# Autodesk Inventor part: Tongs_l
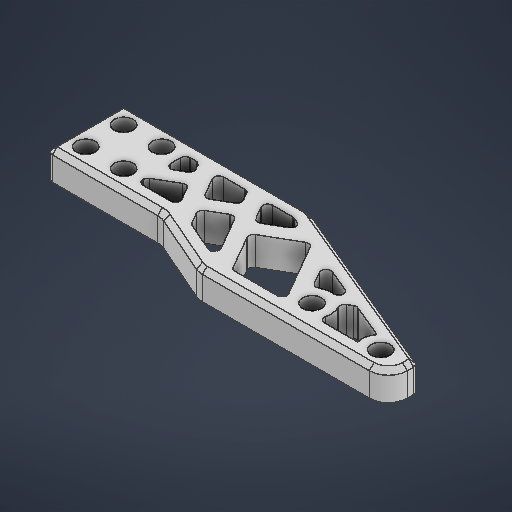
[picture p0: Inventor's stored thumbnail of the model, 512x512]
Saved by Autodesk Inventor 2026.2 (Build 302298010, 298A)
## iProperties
Created: 2026-05
Part Number: Tongs_l
Material: 일반
Document SubType Name: Modeling
Designer: work
Density: 1 g/cm^3
Appearance: 기본값
Author: work
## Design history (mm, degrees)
sketch "스케치1"
  geometry: L1 (-4, 4)-(4, 4); L2 (4, 4)-(4, -4); L3 (4, -4)-(-4, -4); L4 (-4, -4)-(-4, 4); L5 (-4, 4)-(4, -4); L6 (4, 4)-(-4, -4); L7 (-8, 8)-(8, 8); L8 (8, 8)-(8, -8); L9 (8, -8)-(-8, -8); L10 (-8, -8)-(-8, 8); L11 (-8, 8)-(8, -8); L12 (8, 8)-(-8, -8); L13 (-8, 8)-(-16, 8); L14 (-16, 8)-(-29.748, 14); L15 (-29.748, 14)-(-69.748, 14); L16 (-69.748, 14)-(-69.748, 8); L17 (-69.748, 8)-(-31.398, -8); L18 (-31.398, -8)-(-8, -8); L19 (-8, -5)-(-30.797, -5); L20 (-30.797, -5)-(-66.748, 9.999); L21 (-66.748, 9.999)-(-66.748, 11); L22 (-66.748, 11)-(-30.374, 11); L23 (-30.374, 11)-(-16.626, 5); L24 (-16.626, 5)-(-8, 5); L25 (-48.561, 11)-(-42.029, -0.314); L26 (-45.097, 11)-(-37.465, -2.218); L27 (-30.374, 11)-(-21.136, -5); L28 (-33.838, 11)-(-24.6, -5); L29 (-16.626, 5)-(-10.853, -5); L30 (-21.257, 7.021)-(-14.317, -5); L31 (-37.465, -2.218)-(-29.021, 2.657); L32 (-27.521, 0.059)-(-33.982, -3.671); L33 (-13.739, 0)-(-8, 3.314); L34 (-12.239, -2.598)-(-8, -0.15); L35 (-17.787, 1.011)-(-22.902, -1.942); L36 (-24.402, 0.656)-(-19.287, 3.609); L37 (-46.029, 6.614)-(-51.317, 3.561); L38 (-47.029, 8.346)-(-53.639, 4.53); C1 r 2 at (4, 4); C2 r 2 at (4, -4); C3 r 2 at (-4, -4); C4 r 2 at (-4, 4); 4 further points
  constraints: 76 end point, 24 point on line, 19 parallel, 8 midpoint, 6 perpendicular, 4 centre point, 4 coincident, 3 horizontal, 5 other
  dimensions: "d0" = 8 distance of L2.end L3.end; "d1" = 8 distance of L1.end L2.end; "d2" = 4 diameter of C1; "d3" = 4 diameter of C2; "d4" = 4 diameter of C3; "d5" = 4 diameter of C4; "d6" = 4 distance between parallel lines of L8 L2; "d7" = 8 distance of L7.start L13.end; "d8" = 15 distance of L13.end L14.end; "d9" = 40 distance of L14.end L15.end; "d10" = 6 distance of L15.end L16.end; "d11" = 38.34957 horizontal distance of L16.end L17.end; "d12" = 3 distance between parallel lines of L14 L23; "d13" = 3 distance between parallel lines of L25 L26; "d14" = 3 distance between parallel lines of L28 L27; "d15" = 3 distance between parallel lines of L30 L29; "d16" = 120 deg angle of L22 L28; "d17" = 3 distance between parallel lines of L35 L36; "d18" = 3 distance from line of L31 point (-30.752, -1.806); "d19" = 2 distance between parallel lines of L38 L37; "d20" = 8 distance from line of L25.end L37; "d21" = 3 distance between parallel lines of L34 L33
extrude "돌출1" new body sketch "스케치1" distance "d22" = 6; taper "d23" = 0 deg
sketch "스케치2"
  geometry: L1 (16, -8)-(29.748, -14) reference; L2 (29.748, -14)-(69.748, -14) reference; L3 (69.748, -14)-(69.748, -8) reference; L4 (69.748, -8)-(31.398, 8) reference; L5 (31.398, 8)-(-8, 8) reference; L6 (-8, 8)-(-8, -8) reference; L7 (-8, -8)-(16, -8) reference; L8 (27.521, -0.059)-(24.6, 5) reference; L9 (24.6, 5)-(30.797, 5) reference; L10 (30.797, 5)-(33.982, 3.671) reference; L11 (33.982, 3.671)-(27.521, -0.059) reference; L12 (12.239, 2.598)-(8, 0.15) reference; L13 (8, 0.15)-(8, 5) reference; L14 (8, 5)-(10.853, 5) reference; L15 (10.853, 5)-(12.239, 2.598) reference; L16 (17.787, -1.011)-(14.317, 5) reference; L17 (14.317, 5)-(21.136, 5) reference; L18 (21.136, 5)-(22.902, 1.942) reference; L19 (22.902, 1.942)-(17.787, -1.011) reference; L20 (46.029, -6.614)-(42.029, 0.314) reference; L21 (42.029, 0.314)-(51.317, -3.561) reference; L22 (51.317, -3.561)-(46.029, -6.614) reference; L23 (13.739, 0)-(16.626, -5) reference; L24 (16.626, -5)-(8, -5) reference; L25 (8, -5)-(8, -3.314) reference; L26 (8, -3.314)-(13.739, 0) reference; L27 (19.287, -3.609)-(24.402, -0.656) reference; L28 (24.402, -0.656)-(30.374, -11) reference; L29 (30.374, -11)-(21.257, -7.021) reference; L30 (21.257, -7.021)-(19.287, -3.609) reference; L31 (29.021, -2.657)-(37.465, 2.218) reference; L32 (37.465, 2.218)-(45.097, -11) reference; L33 (45.097, -11)-(33.838, -11) reference; L34 (33.838, -11)-(29.021, -2.657) reference; L35 (47.029, -8.346)-(53.639, -4.53) reference; L36 (53.639, -4.53)-(66.748, -9.999) reference; L37 (66.748, -9.999)-(66.748, -11) reference; L38 (66.748, -11)-(48.561, -11) reference; L39 (48.561, -11)-(47.029, -8.346) reference; C1 r 2 at (4, -4) reference; C2 r 2 at (4, 4) reference; C3 r 2 at (-4, 4) reference; C4 r 2 at (-4, -4) reference; 5 further points
  constraints: 4 coincident
hole "구멍1" sketch "스케치2" at (-4, -4), (4, -4), (4, 4), (-4, 4) diameter "d24" = 4; stored, may be unused: countersink angle "d28" = 90 deg, drill point angle "d30" = 118 deg; dims "d25" = 6, "d26" = 6.2, "d27" = 3, "d29" = 8
fillet "모깎기1" dims "d31" = 1
fillet "모깎기2" dims "d32" = 4
fillet "모깎기3" dims "d33" = 1
chamfer "모따기1" distance "d34" = 1; stored, may be unused: second distance "d35" = 2, angle "d36" = 45 deg
node "작업 평면1"
sketch "스케치3"
  geometry: L1 (39.398, 0)-(0, 0) reference; L2 (0, 0)-(80.713, 0); L3 (80.713, 0)-(80.713, 23.103); L4 (80.713, 23.103)-(0, 23.103); L5 (0, 23.103)-(0, 0); 2 further points
  constraints: 8 end point, 2 parallel, 1 horizontal, 1 perpendicular
extrude "돌출2" cut sketch "스케치3" extent not by distance; stored distance "d38" = 10; taper "d39" = 0 deg
fillet "모깎기4" dims "d40" = 1
fillet "모깎기5" dims "d41" = 4
chamfer "모따기2" distance "d42" = 1; stored, may be unused: second distance "d43" = 2, angle "d44" = 45 deg
sketch "스케치4"
  geometry: L1 (77.133, 14.743)-(40.137, -0.692) reference; L2 (77.748, 17)-(77.748, 15.666) reference; L3 (38.583, 21)-(73.748, 21) reference; L4 (24.765, 15.334)-(36.983, 20.666) reference; L5 (1, 15)-(23.165, 15) reference; L6 (0, 0)-(0, 14) reference; L7 (38.597, -1)-(1, -1) reference; L8 (40.232, 4.339)-(36.387, 6.559) reference; L9 (38.982, 2.077)-(40.117, 2.55) reference; L10 (34.332, 2)-(38.597, 2) reference; L11 (35.021, 6.193)-(33.466, 3.5) reference; L12 (16, 5.117)-(16, 3) reference; L13 (19.373, 4.902)-(17.5, 5.984) reference; L14 (19.141, 2.5)-(19.739, 3.536) reference; L15 (17, 2)-(18.275, 2) reference; L16 (30.036, 5.558)-(26.653, 7.511) reference; L17 (29.425, 2.5)-(30.402, 4.192) reference; L18 (24.049, 2)-(28.559, 2) reference; L19 (25.287, 7.145)-(23.183, 3.5) reference; L20 (57.566, 11.572)-(54.895, 13.114) reference; L21 (52.759, 7.825)-(57.451, 9.783) reference; L22 (53.529, 12.748)-(51.508, 9.248) reference; L23 (16.5, 10.025)-(20.873, 7.5) reference; L24 (16, 11)-(16, 10.891) reference; L25 (22.894, 12)-(17, 12) reference; L26 (22.239, 7.866)-(23.76, 10.5) reference; L27 (29.093, 13.736)-(27.787, 11.475) reference; L28 (35.588, 16.784)-(29.559, 14.153) reference; L29 (32.902, 8.522)-(36.854, 15.368) reference; L30 (28.153, 10.109)-(31.536, 8.156) reference; L31 (51.365, 18)-(42.415, 18) reference; L32 (45.965, 5.648)-(52.231, 16.5) reference; L33 (37.887, 9.157)-(44.599, 5.282) reference; L34 (41.549, 17.5)-(37.521, 10.523) reference; L35 (72.153, 18)-(57.138, 18) reference; L36 (62.095, 11.72)-(72.538, 16.077) reference; L37 (55.895, 14.846)-(61.21, 11.777) reference; L38 (56.272, 17.5)-(55.529, 16.212) reference; C1 r 3.1 at (4, 3) reference; C2 r 3.1 at (4, 11) reference; C3 r 3.1 at (12, 11) reference; C4 r 3.1 at (12, 3) reference; C5 r 2 at (56.395, 15.712); C6 r 4 at (56.395, 15.712); C7 r 4 at (72.153, 17); C8 r 2 at (72.153, 17); A1 r 4 centre (38.597, 3) between (38.597, -1) and (40.137, -0.692) reference; A2 r 1 centre (76.748, 15.666) between (77.133, 14.743) and (77.748, 15.666) reference; A3 r 4 centre (73.748, 17) between (77.748, 17) and (73.748, 21) reference; A4 r 4 centre (38.583, 17) between (38.583, 21) and (36.983, 20.666) reference; A5 r 4 centre (23.165, 19) between (23.165, 15) and (24.765, 15.334) reference; A6 r 1 centre (1, 14) between (1, 15) and (0, 14) reference; A7 r 1 centre (1, 0) between (0, 0) and (1, -1) reference; A8 r 1 centre (39.732, 3.473) between (40.117, 2.55) and (40.232, 4.339) reference; A9 r 1 centre (38.597, 3) between (38.597, 2) and (38.982, 2.077) reference; A10 r 1 centre (34.332, 3) between (33.466, 3.5) and (34.332, 2) reference; A11 r 1 centre (35.887, 5.693) between (36.387, 6.559) and (35.021, 6.193) reference; A12 r 1 centre (17, 5.117) between (17.5, 5.984) and (16, 5.117) reference; A13 r 1 centre (18.873, 4.036) between (19.739, 3.536) and (19.373, 4.902) reference; A14 r 1 centre (18.275, 3) between (18.275, 2) and (19.141, 2.5) reference; A15 r 1 centre (17, 3) between (16, 3) and (17, 2) reference; A16 r 1 centre (29.536, 4.692) between (30.402, 4.192) and (30.036, 5.558) reference; A17 r 1 centre (28.559, 3) between (28.559, 2) and (29.425, 2.5) reference; A18 r 1 centre (24.049, 3) between (23.183, 3.5) and (24.049, 2) reference; A19 r 1 centre (26.153, 6.645) between (26.653, 7.511) and (25.287, 7.145) reference; A20 r 1 centre (54.395, 12.248) between (54.895, 13.114) and (53.529, 12.748) reference; A21 r 1 centre (57.066, 10.706) between (57.451, 9.783) and (57.566, 11.572) reference; A22 r 1 centre (52.374, 8.748) between (51.508, 9.248) and (52.759, 7.825) reference; A23 r 1 centre (17, 10.891) between (16, 10.891) and (16.5, 10.025) reference; A24 r 1 centre (17, 11) between (17, 12) and (16, 11) reference; A25 r 1 centre (22.894, 11) between (23.76, 10.5) and (22.894, 12) reference; A26 r 1 centre (21.373, 8.366) between (20.873, 7.5) and (22.239, 7.866) reference; A27 r 1 centre (28.653, 10.975) between (27.787, 11.475) and (28.153, 10.109) reference; A28 r 1 centre (29.959, 13.236) between (29.559, 14.153) and (29.093, 13.736) reference; A29 r 1 centre (35.988, 15.868) between (36.854, 15.368) and (35.588, 16.784) reference; A30 r 1 centre (32.036, 9.022) between (31.536, 8.156) and (32.902, 8.522) reference; A31 r 1 centre (51.365, 17) between (52.231, 16.5) and (51.365, 18) reference; A32 r 1 centre (45.099, 6.148) between (44.599, 5.282) and (45.965, 5.648) reference; A33 r 1 centre (38.387, 10.023) between (37.521, 10.523) and (37.887, 9.157) reference; A34 r 1 centre (42.415, 17) between (42.415, 18) and (41.549, 17.5) reference; A35 r 1 centre (72.153, 17) between (72.538, 16.077) and (72.153, 18) reference; A36 r 1 centre (61.71, 12.643) between (61.21, 11.777) and (62.095, 11.72) reference; A37 r 1 centre (56.395, 15.712) between (55.529, 16.212) and (55.895, 14.846) reference; A38 r 1 centre (57.138, 17) between (57.138, 18) and (56.272, 17.5) reference; 11 further points
  constraints: 4 centre point, 4 coincident
  dimensions: "d45" = 4 diameter of C5; "d46" = 8 diameter of C6; "d47" = 8 diameter of C7; "d48" = 4 diameter of C8
  node "투영된 루프2"
extrude "돌출3" join sketch "스케치4" stored distance "d49" = 10; taper "d50" = 0 deg
extrude "돌출4" cut sketch "스케치4" extent not by distance; stored distance "d51" = 10; taper "d52" = 0 deg
fillet "모깎기6" dims "d53" = 1
sketch "스케치5"
  geometry: C1 r 2 at (56.395, 15.712) reference; C2 r 2 at (72.153, 17) reference; 4 further points
  constraints: 2 coincident
hole "구멍2" sketch "스케치5" at (56.395, 15.712), (72.153, 17) diameter "d54" = 4; stored, may be unused: countersink angle "d58" = 90 deg, drill point angle "d60" = 118 deg; dims "d55" = 6, "d56" = 6.2, "d57" = 3, "d59" = 8
node "솔리드1"
mirror "미러1"
node "투영된 루프1"
feature "A9D066F2-1C7D-4E18-AEED-F7BC21143FA4" dims "d24" = 4, "d25" = 6, "d26" = 6.2, "d27" = 3, "d28" = 90 deg, "d29" = 8, "d30" = 118 deg
other parameters: "d37" = 0
